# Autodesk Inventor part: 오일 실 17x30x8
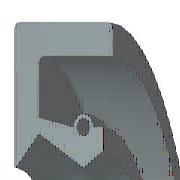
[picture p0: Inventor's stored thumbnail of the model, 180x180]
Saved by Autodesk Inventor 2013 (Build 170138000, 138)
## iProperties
IsCustomPart: 1
Created: 2012-02
Part Number: 오일 실 17x30x8
Material: 고무
Description: 오일-실
Document SubType Name: Modeling
Standard: KS B 2804
Designer: mduedu
Standards Organization: KS
Language: ko-KR
Size Designation: D - 17 30 8
Categories: <MemberInstance><Categories><Category DisplayName="샤프트 부품" InternalName="7f7aeb1f-a693-4053-b835-cee3144e0d98" Mnemonic="SHFT"><Category DisplayName="실링" Intern
Density: 0.93 g/cm^3
Author: mduedu
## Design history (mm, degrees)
revolve "본체" stored, may be unused: angle "d17" = 90 deg
revolve "스프링1" stored, may be unused: angle "d18" = 90 deg
body "Solid1"
sketch "스케치1"
  geometry: L1 (0, 15)-(8, 15); L2 (8, 13.25)-(1.75, 13.25); L3 (1.75, 10.25)-(4.9, 8.5); L4 (4.9, 8.5)-(0, 8.5); L5 (0, 0)-(9.586, 0) reference; L6 (4.9, 8.5)-(6.3, 9.375); L7 (0, 18)-(0, -3) reference; L8 (-1.941, 0)-(11.507, 0) reference; L9 (4.2, 10.6)-(1.75, 11.21); L10 (1.75, 11.21)-(1.75, 13.25); L11 (0, 15)-(0, 8.588); L12 (4.9, 8.5)-(0, 8.5); L13 (1.75, 10.25)-(0.152, 8.528); L14 (8, 15)-(8, 13.25); L15 (5.6, 10.6)-(6.3, 10.6); L16 (6.3, 10.6)-(6.3, 9.375); C1 r 0.455 at (4.9, 10.6); A1 r 0.7 centre (4.9, 10.6) between (5.6, 10.6) and (4.2, 10.6); A2 r 0.088 centre (0.088, 8.588) between (0, 8.588) and (0.152, 8.528); 1 further point
  constraints: 28 end point, 5 horizontal alignment, 5 point on line, 4 point on circle, 4 vertical alignment, 3 centre point, 3 tangent, 2 collinear, 2 horizontal, 2 perpendicular, 1 coincident, 1 parallel
  dimensions: "d0" = 30 diameter of L1 L5 (= SD2); "d1" = 1.75 distance of L1.end L2.start (= SD); "d2" = 0.91 diameter of C1 (= SPDI); "d3" = 1.4 diameter of A1 (= SPDA); "d4" = 17 diameter of L3.end L5 (= NND); "d5" = 20.5 diameter of L3.start L5 (= TKDM); "d7" = 22.42 diameter of L9.end L5 (= TKDM + 0.24 x SWDT); "d8" = 1.75 distance between parallel lines of L11 L10 (= SD); "d9" = 4.9 distance from line of L11 C1.centre (= SPDST); "d10" = 21.2 diameter of C1.centre L5 (= HLDM); "d11" = 0.0875 radius of A2 (= 0.25 x LAB); "d12" = 6.3 distance between parallel lines of L11 L16 (= SDI); "d13" = 18.75 diameter of L6.end L5 (= ABDM); "d14" = 8 distance from line of L11 L1.end (= SWDT)
fillet "모깎기1" dims "d6" = 0.3 (= RR)
other parameters: "SD2" = 30 [user parameter; used in 1 equation term], "SWDT" = 8 [user parameter; used in 2 equation terms], "RR" = 0.3 [user parameter; used in 1 equation term], "SD" = 1.75 [user parameter; used in 2 equation terms], "NND" = 17 [user parameter; used in 1 equation term], "SPDA" = 1.4 [user parameter; used in 1 equation term], "SPDI" = 0.91 [user parameter; used in 1 equation term], "TKDM" = 20.5 [user parameter; used in 2 equation terms], "HLDM" = 21.2 [user parameter; used in 1 equation term], "ABDM" = 18.75 [user parameter; used in 1 equation term], "SDI" = 6.3 [user parameter; used in 1 equation term], "SPDST" = 4.9 [user parameter; used in 1 equation term], "LAB" = 0.35 [user parameter; used in 1 equation term], "d15" = 0, "d16" = 0, "d19" = 0
